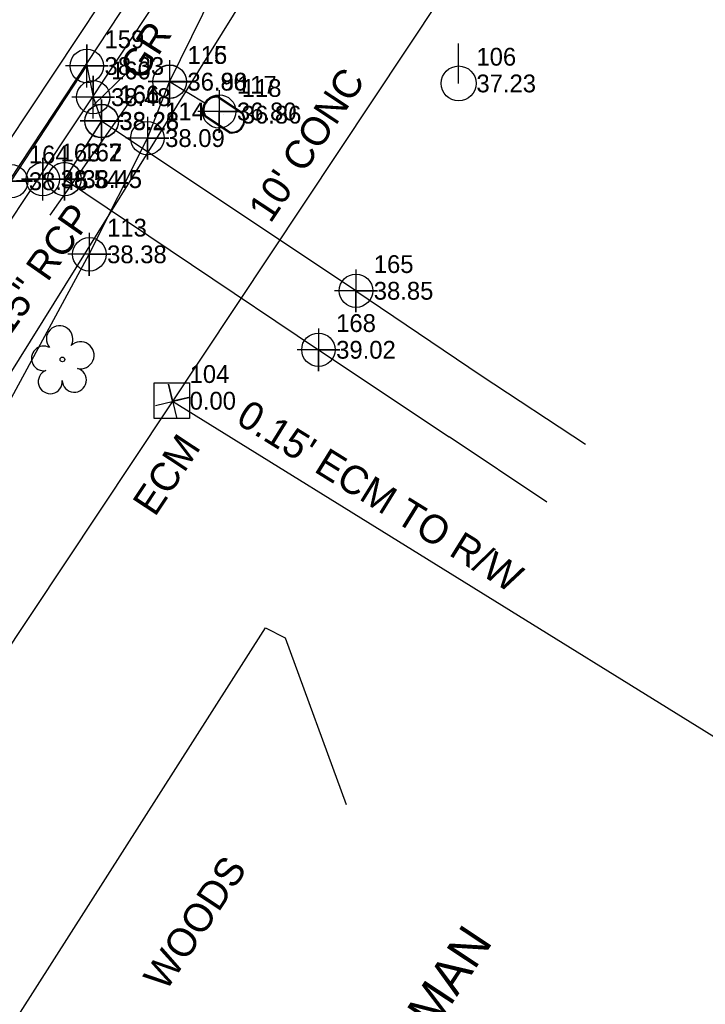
# Model space of a CAD drawing. Extents: x 2603627 to 2605187, y 896619 to 899063.
# Drawn here: x 2604120.7 to 2604216.9, y 897380.8 to 897519.1 of the extents above; entities that cross this region are included whole.
import ezdxf

# ---------------------------------------------------------------- set-up
doc = ezdxf.new("R2010")
doc.units = 0
for name, color, linetype in [('Exist Horizontal Baseline Alignment', 7, 'Continuous'), ('Exist Property Corner CELL', 7, 'Continuous'), ('Exist Property Line', 7, 'Continuous'), ('Exist Property Line Text', 7, 'Continuous'), ('Exist Property Monument CELL', 7, 'Continuous'), ('Exist Property Monument Cogo Elevation', 7, 'Continuous'), ('Exist Property Monument Cogo Number', 7, 'Continuous'), ('Exist Property Monument Text', 7, 'Continuous'), ('Exist Property Owner Text', 7, 'Continuous'), ('Exist Right of Way Line', 7, 'Continuous'), ('Exist Roads EOP', 7, 'Continuous'), ('Exist Roads EOP Other', 7, 'Continuous'), ('Exist Roads EOP Other Cogo Elevation', 7, 'Continuous'), ('Exist Roads EOP Other Cogo Number', 7, 'Continuous'), ('Exist Roads EOP Other Cogo Point CELL', 7, 'Continuous'), ('Exist Roads EOP Other Text', 7, 'Continuous'), ('Exist Roads EOT', 7, 'Continuous'), ('Exist Roads Soil', 7, 'Continuous'), ('Exist Roads Soil Cogo Elevation', 7, 'Continuous'), ('Exist Roads Soil Cogo Number', 7, 'Continuous'), ('Exist Roads Soil Cogo Point CELL', 7, 'Continuous'), ('Exist Roads Soil Leader', 7, 'Continuous'), ('Exist Roads Soil Text', 7, 'Continuous'), ('Exist Structure Minor Pipes RCP 15 Inch', 7, 'Continuous'), ('Exist Structure Minor Pipes RCP 15 Inch Text', 7, 'Continuous'), ('Exist Utilities Power Pole CELL', 7, 'Continuous'), ('Exist Utilities Power Pole Cogo Elevation', 7, 'Continuous'), ('Exist Utilities Power Pole Cogo Number', 7, 'Continuous'), ('Exist Utilities Telephone UG Cable SUE LOS C', 7, 'Continuous'), ('Exist Utilities Water Meter CELL', 7, 'Continuous'), ('Exist Utilities Water Meter Cogo Elevation', 7, 'Continuous'), ('Exist Utilities Water Meter Cogo Number', 7, 'Continuous'), ('Exist Utilities Water UG Line SUE LOS B', 7, 'Continuous'), ('Exist Utilities Water UG Line SUE LOS B Cogo Elevation', 7, 'Continuous'), ('Exist Utilities Water UG Line SUE LOS B Cogo Number', 7, 'Continuous'), ('Exist Utilities Water UG Line SUE LOS B Cogo Point CELL', 7, 'Continuous'), ('Exist Vegetation Tree CELL', 7, 'Continuous'), ('Exist Vegetation Woods Line', 7, 'Continuous'), ('Exist Vegetation Woods Line Text', 7, 'Continuous')]:
    doc.layers.add(name, color=color, linetype=linetype)

# ---------------------------------------------------------------- blocks, each defined once
blk = doc.blocks.new('EXIST UTILITIES WATER UG LINE SUE LOS B COGO POINT')
at = {"layer": 'Exist Utilities Water UG Line SUE LOS B Cogo Point CELL'}
blk.add_lwpolyline([(0, 0.06), (0, -0.06), (0, 0), (0.06, 0), (-0.06, 0)], dxfattribs=at)
blk.add_circle((0, 0), 0.0469, dxfattribs=at)
blk = doc.blocks.new('EXIST UTILITIES WATER METER')
at = {"layer": 'Exist Utilities Water Meter CELL'}
blk.add_line((0, 0), (0, 0), dxfattribs=at)
for points in [[(-0.0408, 0.034), (0.0408, 0.034)], [(-0.0408, 0.0312), (0.0408, 0.0312)], [(0.0408, -0.0312), (-0.0413, -0.0312)], [(0.0408, -0.034), (-0.0413, -0.034)]]:
    blk.add_lwpolyline(points, dxfattribs=at)
for centre, radius, start, end in [((-0.0261, -0.0001), 0.0371, 113.178, 245.9794), ((-0.0259, -0.0001), 0.0347, 115.3009, 243.7824), ((0.0259, 0), 0.0371, 293.6483, 66.3084), ((0.0261, 0), 0.0345, 295.1272, 64.8728)]:
    blk.add_arc(centre, radius, start, end, dxfattribs=at)
blk = doc.blocks.new('EXIST ROADS SOIL COGO POINT')
at = {"layer": 'Exist Roads Soil Cogo Point CELL'}
blk.add_lwpolyline([(0, -0.06), (0, 0.06), (0, 0), (0.06, 0), (-0.06, 0)], dxfattribs=at)
blk.add_circle((0, 0), 0.0469, dxfattribs=at)
blk = doc.blocks.new('EXIST ROADS EOP OTHER COGO POINT')
at = {"layer": 'Exist Roads EOP Other Cogo Point CELL'}
blk.add_lwpolyline([(0, 0.06), (0, -0.06), (0, 0), (0.06, 0), (-0.06, 0)], dxfattribs=at)
blk.add_circle((0, 0), 0.0469, dxfattribs=at)
blk = doc.blocks.new('EXIST PROPERTY MONUMENT')
at = {"layer": 'Exist Property Monument CELL'}
blk.add_line((0, 0), (0, 0), dxfattribs=at)
blk.add_lwpolyline([(-0.0499, -0.0499), (-0.0499, 0.0499), (0.0499, 0.0499), (0.0499, -0.0499), (-0.0499, -0.0499)], dxfattribs=at)

msp = doc.modelspace()

# ---------------------------------------------------------------- linework, layer by layer
at = {"layer": 'Exist Horizontal Baseline Alignment'}
msp.add_line((2604070.2, 897390.44), (2604301.74, 897762.53), dxfattribs=at)
at = {"layer": 'Exist Property Corner CELL'}
msp.add_line((2604142.16, 897465.52), (2604142.16, 897465.52), dxfattribs=at)
msp.add_lwpolyline([(2604139.73, 897464.94), (2604144.6, 897466.09), (2604142.16, 897465.52), (2604141.59, 897467.95), (2604142.74, 897463.08)], dxfattribs=at)
at = {"layer": 'Exist Property Line'}
msp.add_line((2604142.16, 897465.52), (2604357.51, 897332.06), dxfattribs=at)
at = {"layer": 'Exist Right of Way Line'}
msp.add_line((2604087.98, 897383.94), (2604542.77, 898068.69), dxfattribs=at)
at = {"layer": 'Exist Roads EOP'}
msp.add_lwpolyline([(2604057.72, 897404.05), (2604078.22, 897434.83), (2604108.36, 897480.05), (2604137.93, 897524.86), (2604167.35, 897568.96), (2604196.06, 897612.17), (2604224.86, 897655.68), (2604253.51, 897698.95), (2604283.96, 897744.64), (2604314.74, 897791.03), (2604343.97, 897835.34), (2604373.31, 897879.6), (2604402.1, 897923.18), (2604431.64, 897967.59), (2604461.24, 898012.02), (2604491.05, 898056.88), (2604519.7, 898100.47)], dxfattribs=at)
at = {"layer": 'Exist Roads EOP Other'}
for p, q in [((2604167.9, 897481.05), (2604185.48, 897469.15)), ((2604162.62, 897472.76), (2604180.99, 897460.52))]:
    msp.add_line(p, q, dxfattribs=at)
for points in [[(2604167.9, 897481.05), (2604132.19, 897504.86), (2604126.99, 897496.73), (2604162.62, 897472.76)], [(2604185.48, 897469.15), (2604200.12, 897459.51)], [(2604194.71, 897451.36), (2604180.99, 897460.52)]]:
    msp.add_lwpolyline(points, dxfattribs=at)
at = {"layer": 'Exist Roads EOT'}
msp.add_lwpolyline([(2604055.13, 897405.77), (2604075.39, 897436.3), (2604105.72, 897481.84), (2604135.41, 897526.58), (2604164.51, 897570.47), (2604193.14, 897613.84), (2604222.02, 897657.58), (2604250.73, 897700.63), (2604281.08, 897746.07), (2604311.9, 897792.56), (2604341.37, 897836.94), (2604370.82, 897881.24), (2604399.64, 897924.71), (2604429.03, 897968.88), (2604458.85, 898013.95), (2604488.44, 898058.33), (2604517.14, 898101.52)], dxfattribs=at)
at = {"layer": 'Exist Roads Soil'}
msp.add_lwpolyline([(2604130.1, 897512.63), (2604131.01, 897508.25), (2604132.19, 897504.92), (2604126.99, 897496.75), (2604123.93, 897496.72), (2604119.47, 897496.44), (2604130.1, 897512.63)], dxfattribs=at)
at = {"layer": 'Exist Roads Soil Leader'}
msp.add_line((2604131.09, 897507.15), (2604135.83, 897511.76), dxfattribs=at)
at = {"layer": 'Exist Structure Minor Pipes RCP 15 Inch'}
msp.add_line((2604124.95, 897491.67), (2604136.58, 897508.22), dxfattribs=at)
at = {"layer": 'Exist Utilities Power Pole CELL'}
for q in [(2604182.31, 897515.81), (2604182.31, 897510.18)]:
    msp.add_line((2604182.31, 897510.18), q, dxfattribs=at)
msp.add_circle((2604182.31, 897510.18), 2.45, dxfattribs=at)
at = {"layer": 'Exist Utilities Telephone UG Cable SUE LOS C'}
msp.add_line((2604060.46, 897402.24), (2604201.56, 897614.6), dxfattribs=at)
at = {"layer": 'Exist Utilities Water UG Line SUE LOS B'}
msp.add_line((2604141.74, 897510.43), (2604146.68, 897507.45), dxfattribs=at)
msp.add_lwpolyline([(2604076.5, 897391.6), (2604089.19, 897412.44), (2604108.02, 897444.81), (2604130.46, 897486.17), (2604138.61, 897502.5), (2604141.74, 897510.42), (2604157.29, 897542.11), (2604195.61, 897598.86), (2604232.99, 897655.2), (2604269.72, 897709.19), (2604303.43, 897758.71), (2604343.24, 897819.02), (2604371.6, 897861.28), (2604402.52, 897906.63), (2604434.42, 897955.25), (2604460.63, 897996.69), (2604477.79, 898022.59), (2604502.25, 898059.64), (2604529.4, 898098.89), (2604530.47, 898100.43), (2604537.02, 898109.88), (2604550.55, 898129.28)], dxfattribs=at)
at = {"layer": 'Exist Vegetation Tree CELL'}
msp.add_line((2604126.68, 897471.4), (2604126.68, 897471.4), dxfattribs=at)
msp.add_circle((2604126.68, 897471.4), 0.326, dxfattribs=at)
for centre, radius, start, end in [((2604126.29, 897474.27), 1.86, 330.1651, 219.7134), ((2604124.07, 897471.55), 1.73, 62.6636, 279.3457), ((2604129.23, 897471.99), 1.9, 257.1011, 134.1999), ((2604124.98, 897468.28), 1.69, 111.5671, 6.231), ((2604128.35, 897468.5), 1.7, 181.2822, 74.56)]:
    msp.add_arc(centre, radius, start, end, dxfattribs=at)
at = {"layer": 'Exist Vegetation Woods Line'}
msp.add_lwpolyline([(2604112.93, 897367.45), (2604155.21, 897433.72), (2604157.95, 897432.28), (2604166.53, 897408.86)], dxfattribs=at)

# ---------------------------------------------------------------- block references
at = {"layer": 'Exist Property Monument CELL', "xscale": 50, "yscale": 50}
msp.add_blockref('EXIST PROPERTY MONUMENT', (2604142.04, 897465.6), dxfattribs=at)
at = {"layer": 'Exist Roads EOP Other Cogo Point CELL', "xscale": 50, "yscale": 50}
for p in [(2604132.19, 897504.86), (2604126.99, 897496.73), (2604167.9, 897481.05), (2604162.62, 897472.76)]:
    msp.add_blockref('EXIST ROADS EOP OTHER COGO POINT', p, dxfattribs=at)
at = {"layer": 'Exist Roads Soil Cogo Point CELL', "xscale": 50, "yscale": 50}
for p in [(2604130.1, 897512.63), (2604131.01, 897508.25), (2604132.19, 897504.92), (2604119.47, 897496.44), (2604123.93, 897496.72), (2604126.99, 897496.75)]:
    msp.add_blockref('EXIST ROADS SOIL COGO POINT', p, dxfattribs=at)
at = {"layer": 'Exist Utilities Water Meter CELL', "xscale": 50.00000000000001, "yscale": 50, "rotation": -33.81503921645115}
msp.add_blockref('EXIST UTILITIES WATER METER', (2604149.36, 897505.78), dxfattribs=at)
at = {"layer": 'Exist Utilities Water UG Line SUE LOS B Cogo Point CELL', "xscale": 50, "yscale": 50}
for p in [(2604141.74, 897510.43), (2604141.74, 897510.42), (2604148.69, 897506.24), (2604138.61, 897502.5), (2604130.46, 897486.17)]:
    msp.add_blockref('EXIST UTILITIES WATER UG LINE SUE LOS B COGO POINT', p, dxfattribs=at)

# ---------------------------------------------------------------- texts
at = {"layer": 'Exist Property Line Text'}
for s, rotation, p in [("0.01' ECM TO R/W", 327.5958, (2604198.67, 897541.14)), ("0.15' ECM TO R/W", 328.2125, (2604150.86, 897462.54))]:
    msp.add_text(s, height=4, rotation=rotation, dxfattribs=at).set_placement(p)
at = {"layer": 'Exist Property Monument Cogo Elevation'}
msp.add_text('0.00', height=2.5, dxfattribs=at).set_placement((2604144.54, 897464.35))
at = {"layer": 'Exist Property Monument Cogo Number'}
msp.add_text('104', height=2.5, dxfattribs=at).set_placement((2604144.54, 897468.1))
at = {"layer": 'Exist Property Monument Text'}
msp.add_text('ECM', height=4, rotation=56.4785, dxfattribs=at).set_placement((2604139.67, 897449.17))
at = {"layer": 'Exist Property Owner Text'}
msp.add_text('ALFRED FREEMAN', height=5, rotation=56.4133, dxfattribs=at).set_placement((2604153.49, 897338.79))
at = {"layer": 'Exist Roads EOP Other Cogo Elevation'}
for s, p in [('38.28', (2604134.69, 897503.61)), ('38.45', (2604129.49, 897495.48)), ('38.85', (2604170.4, 897479.8)), ('39.02', (2604165.12, 897471.51))]:
    msp.add_text(s, height=2.5, dxfattribs=at).set_placement(p)
at = {"layer": 'Exist Roads EOP Other Cogo Number'}
for s, p in [('166', (2604134.69, 897507.36)), ('167', (2604129.49, 897499.23)), ('165', (2604170.4, 897483.55)), ('168', (2604165.12, 897475.26))]:
    msp.add_text(s, height=2.5, dxfattribs=at).set_placement(p)
at = {"layer": 'Exist Roads EOP Other Text'}
msp.add_text("10' CONC", height=4, rotation=56.3361, dxfattribs=at).set_placement((2604155.89, 897490.4))
at = {"layer": 'Exist Roads Soil Cogo Elevation'}
for s, p in [('38.33', (2604132.6, 897511.38)), ('38.48', (2604133.51, 897507)), ('38.28', (2604134.69, 897503.67)), ('38.54', (2604126.43, 897495.47)), ('38.45', (2604129.49, 897495.5)), ('38.45', (2604121.97, 897495.19))]:
    msp.add_text(s, height=2.5, dxfattribs=at).set_placement(p)
at = {"layer": 'Exist Roads Soil Cogo Number'}
for s, p in [('159', (2604132.6, 897515.13)), ('160', (2604133.51, 897510.75)), ('161', (2604134.69, 897507.42)), ('164', (2604121.97, 897498.94)), ('163', (2604126.43, 897499.22)), ('162', (2604129.49, 897499.25))]:
    msp.add_text(s, height=2.5, dxfattribs=at).set_placement(p)
at = {"layer": 'Exist Roads Soil Text'}
msp.add_text('GR', height=4, rotation=57.5701, dxfattribs=at).set_placement((2604137.88, 897510.38))
at = {"layer": 'Exist Structure Minor Pipes RCP 15 Inch Text'}
msp.add_text('15" RCP', height=4, rotation=54.9355, dxfattribs=at).set_placement((2604119.23, 897474.53))
at = {"layer": 'Exist Utilities Power Pole Cogo Elevation'}
msp.add_text('37.23', height=2.5, dxfattribs=at).set_placement((2604184.81, 897508.93))
at = {"layer": 'Exist Utilities Power Pole Cogo Number'}
msp.add_text('106', height=2.5, dxfattribs=at).set_placement((2604184.81, 897512.68))
at = {"layer": 'Exist Utilities Water Meter Cogo Elevation'}
msp.add_text('36.86', height=2.5, dxfattribs=at).set_placement((2604151.86, 897504.54))
at = {"layer": 'Exist Utilities Water Meter Cogo Number'}
msp.add_text('118', height=2.5, dxfattribs=at).set_placement((2604151.86, 897508.29))
at = {"layer": 'Exist Utilities Water UG Line SUE LOS B Cogo Elevation'}
for s, p in [('36.88', (2604144.24, 897509.18)), ('36.90', (2604144.24, 897509.17)), ('36.80', (2604151.19, 897504.99)), ('38.09', (2604141.11, 897501.25)), ('38.38', (2604132.96, 897484.92))]:
    msp.add_text(s, height=2.5, dxfattribs=at).set_placement(p)
at = {"layer": 'Exist Utilities Water UG Line SUE LOS B Cogo Number'}
for s, p in [('116', (2604144.24, 897512.93)), ('115', (2604144.24, 897512.92)), ('117', (2604151.19, 897508.74)), ('114', (2604141.11, 897505)), ('113', (2604132.96, 897488.67))]:
    msp.add_text(s, height=2.5, dxfattribs=at).set_placement(p)
at = {"layer": 'Exist Vegetation Woods Line Text'}
msp.add_text('WOODS', height=4, rotation=56.4094, dxfattribs=at).set_placement((2604141.19, 897382.49))

doc.saveas('drawing.dxf')
